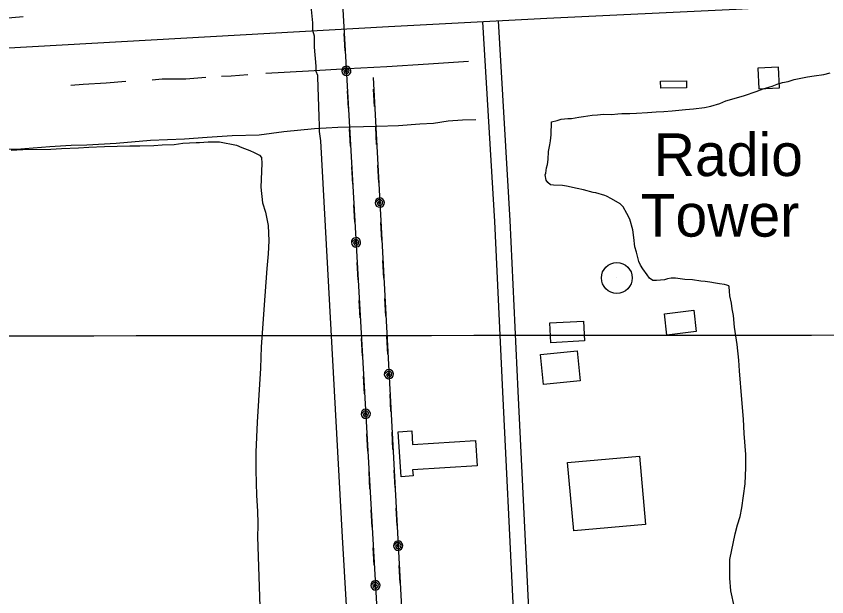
# Model space of a CAD drawing. Extents: x 3297716 to 3335574, y 688621 to 713991.
# Drawn here: x 3314736 to 3316312, y 708656 to 709785 of the extents above; entities that cross this region are included whole.
import ezdxf

# ---------------------------------------------------------------- set-up
doc = ezdxf.new("R2010")
doc.units = 0
for name, color, linetype in [('V-BLDG-OTLN', 7, 'Continuous'), ('V-GRID-MAJR', 7, 'Continuous'), ('V-ROAD-CNTR', 7, 'Continuous'), ('V-SITE-VEGE', 7, 'Continuous'), ('V-TOPO-SHOR', 7, 'Continuous'), ('V-TOPO-TOWR', 7, 'Continuous'), ('V-TOPO-TOWR-IDEN', 7, 'Continuous'), ('V-UTIL-LINE', 7, 'Continuous')]:
    doc.layers.add(name, color=color, linetype=linetype)

msp = doc.modelspace()

# ---------------------------------------------------------------- linework, layer by layer
at = {"layer": 'V-BLDG-OTLN'}
for points in [[(3316218.3325259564, 709685.3546023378), (3316178.382605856, 709683.3426063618), (3316180.39560183, 709643.39368626), (3316220.3445219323, 709645.405682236)], [(3315989.273984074, 709658.4176562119), (3316039.2688840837, 709659.0846548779), (3316039.45588371, 709645.085682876), (3315989.459983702, 709644.4196842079)], [(3315996.468969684, 709205.845561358), (3316053.463855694, 709212.7065476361), (3316058.452845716, 709171.2626305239), (3316001.4579597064, 709164.4016442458)], [(3315841.0712804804, 709153.1896666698), (3315775.5654114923, 709149.7616735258), (3315773.549415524, 709188.285596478), (3315839.055284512, 709191.713589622)], [(3315833.012296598, 709075.461822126), (3315761.378439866, 709068.3098364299), (3315755.5644514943, 709126.5387199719), (3315827.198308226, 709133.6917056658)], [(3315507.0640000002, 708951.895), (3315629.5470000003, 708959.637), (3315632.666, 708910.272), (3315507.111, 708902.338), (3315507.858, 708890.5), (3315484.728, 708889.04), (3315479.207, 708976.406), (3315505.411, 708978.058)], [(3315959.65604331, 708796.4103802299), (3315820.252322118, 708784.007405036), (3315808.4523457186, 708916.6331397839), (3315947.85606691, 708929.0361149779)]]:
    msp.add_lwpolyline(points, close=True, dxfattribs=at)
at = {"layer": 'V-GRID-MAJR'}
msp.add_spline([(3301840.245, 709153.404), (3307091.973, 709156.841), (3312343.699, 709161.042), (3317595.4250000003, 709166.008), (3322847.151, 709171.736), (3328098.875, 709178.229), (3333350.598, 709185.486), (3333350.599, 709185.486)], degree=3, dxfattribs=at)
at = {"layer": 'V-ROAD-CNTR'}
for points in [[(3321969.11902436, 710116.1787406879), (3321666.245630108, 710108.8057554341), (3321492.746977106, 710098.0457769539), (3321073.9358147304, 710068.725835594), (3320654.183654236, 710049.840873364), (3320230.1515023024, 710028.8209154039), (3319711.4135397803, 709997.8059774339), (3319431.537099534, 709981.7200096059), (3319189.123584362, 709967.2580385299), (3318433.2280961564, 709928.030116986), (3318142.237678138, 709911.7191496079), (3317361.76323909, 709865.509242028), (3316719.677523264, 709830.5803118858), (3316136.331689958, 709797.4653781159), (3315767.733427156, 709780.235412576), (3315460.47704167, 709764.0894448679), (3314594.6517733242, 709715.615541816), (3313764.1424343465, 709666.735639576), (3313139.8856828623, 709630.3297123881), (3312580.6778012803, 709600.1097728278), (3311894.166174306, 709563.750845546), (3311218.8075250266, 709524.6229238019), (3310603.397755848, 709491.00399104), (3310297.884366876, 709478.5810158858)], [(3315643.158676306, 709773.591425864), (3315666.083630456, 709385.522202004), (3315681.919598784, 709054.0518649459), (3315701.758559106, 708643.1946866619), (3315726.4265097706, 708269.513434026), (3315739.108484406, 708212.2485485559), (3315764.9624326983, 708155.707661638), (3315803.2323561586, 708088.212796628), (3315841.983278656, 708033.1759067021), (3315900.6751612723, 707990.2989924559), (3316040.284882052, 707884.6312037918), (3316095.7847710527, 707831.3283103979), (3316137.516687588, 707782.1574087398), (3316169.0516245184, 707726.604519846), (3316190.167582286, 707676.48762008), (3316201.601559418, 707620.7597315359), (3316210.474541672, 707465.8600413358), (3316221.8445189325, 707144.790683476), (3316229.917502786, 706954.1030648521)], [(3315673.1066164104, 709775.361422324), (3315696.04157054, 709387.1221988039), (3315711.885538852, 709055.4918620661), (3315731.710499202, 708644.906683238), (3315756.210450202, 708273.769425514), (3315767.7124271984, 708221.8365293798), (3315791.7023792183, 708169.3696343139), (3315828.6063054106, 708104.2847644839), (3315863.669235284, 708054.4858640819), (3315918.5771254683, 708014.3729443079), (3316059.794843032, 707907.4891580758), (3316117.668727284, 707851.9062692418), (3316162.214638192, 707799.4193742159), (3316196.011570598, 707739.8784932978), (3316218.9615246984, 707685.411602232), (3316231.4274997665, 707624.6537237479), (3316240.4444817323, 707467.2480385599), (3316251.822458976, 707145.956681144), (3316259.8914428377, 706955.371062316)]]:
    msp.add_lwpolyline(points, dxfattribs=at)
at = {"layer": 'V-SITE-VEGE'}
for points in [[(3315923.807, 709401.017), (3315916.5, 709413.66), (3315910.237, 709419.759), (3315893.714, 709429.509), (3315884.154, 709434.435), (3315880.9590000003, 709435.86), (3315862.9590000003, 709441.1190000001), (3315857.79, 709441.971), (3315839.143, 709447.255), (3315826.884, 709449.688), (3315806.2600000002, 709454.397), (3315798.4960000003, 709455.351), (3315780.967, 709456.037), (3315775.149, 709456.9180000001), (3315770.109, 709461.0160000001), (3315766.392, 709465.714), (3315764.852, 709476.177), (3315766.2770000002, 709479.372), (3315767.3340000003, 709489.737), (3315769.538, 709496.149), (3315770.568, 709505.863), (3315771.178, 709521.444), (3315773.636, 709534.353), (3315775.239, 709542.0920000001), (3315776.347, 709553.751), (3315777.34, 709579.071), (3315787.857, 709581.909), (3315795.7460000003, 709584.201), (3315808.808, 709585.6410000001), (3315815.9760000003, 709586.007), (3315830.359, 709588.045), (3315839.526, 709589.636), (3315855.883, 709592.245), (3315866.322, 709593.136), (3315878.057, 709593.976), (3315893.6380000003, 709593.366), (3315906.051, 709594.83), (3315913.8680000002, 709595.172), (3315929.472, 709595.213), (3315942.5100000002, 709595.9990000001), (3315964.0100000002, 709597.107), (3315980.316, 709598.4180000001), (3315995.299, 709599.131), (3316011.605, 709600.441), (3316037.727, 709603.319), (3316053.384, 709604.654), (3316074.286, 709607.085), (3316086.748, 709609.848), (3316104.506, 709615.003), (3316115.748, 709619.764), (3316136.801, 709626.091), (3316152.5870000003, 709630.672), (3316174.99, 709638.248), (3316188.853, 709643.556), (3316205.9620000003, 709648.735), (3316215.8540000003, 709652.25), (3316226.393, 709655.737), (3316236.8850000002, 709657.927), (3316248.72, 709661.363), (3316258.561, 709663.577), (3316274.9450000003, 709666.838), (3316287.383, 709668.949), (3316306.3370000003, 709671.458), (3316318.799, 709674.221)], [(3314726.3910000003, 709524.0650000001), (3314749.1890000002, 709525.12), (3314803.85, 709526.228), (3314824.699, 709527.361), (3314857.2660000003, 709528.684), (3314877.466, 709529.843), (3314908.0810000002, 709531.242), (3314957.549, 709532.552), (3314977.0500000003, 709532.438), (3315003.741, 709533.343), (3315020.052, 709534.654), (3315043.474, 709535.035), (3315060.481, 709537.617), (3315086.5500000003, 709539.196), (3315093.042, 709538.942), (3315109.35, 709540.253), (3315117.815, 709540.5700000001), (3315131.448, 709540.036), (3315164.356, 709533.544), (3315175.239, 709529.214), (3315190.615, 709523.41), (3315198.93, 709519.832), (3315209.113, 709514.233), (3315213.504, 709510.16), (3315213.694, 709498.447), (3315211.8880000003, 709452.353), (3315215.234, 709421.661), (3315221.014, 709403.229), (3315226.512, 709377.656), (3315227.289, 709347.714), (3315226.295, 709322.397), (3315223.877, 709293.88), (3315219.84, 709240.723), (3315212.699, 709141.52), (3315211.068, 709099.97), (3315207.3000000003, 709037.047), (3315204.994, 708994.875), (3315202.082, 708937.1190000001), (3315202.002, 708902.01), (3315203.313, 708852.5430000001), (3315205.363, 708821.902), (3315206.3680000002, 708797.806), (3315205.221, 708768.591), (3315206.088, 708757.503), (3315205.934, 708753.608), (3315209.7660000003, 708635.77)], [(3316133.023, 708634.664), (3316125.857, 708667.457), (3316123.553, 708691.605), (3316123.682, 708728.012), (3316134.106, 708778.319), (3316138.69, 708795.694), (3316143.8710000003, 708811.746), (3316147.129, 708828.5260000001), (3316153.509, 708875.089), (3316154.756, 708906.9010000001), (3316155.1, 708932.247), (3316151.5100000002, 708973.35), (3316150.634, 709000.6950000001), (3316146.941, 709039.201), (3316142.6380000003, 709095.2880000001), (3316141.481, 709115.4890000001), (3316138.1350000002, 709146.181), (3316132.965, 709180.196), (3316130.586, 709202.3960000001), (3316128.4990000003, 709215.483), (3316126.983, 709226.595), (3316123.647, 709241.03), (3316123.358, 709250.145), (3316122.3880000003, 709258.636), (3316121.8140000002, 709260.609), (3316117.9450000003, 709261.411), (3316113.452, 709262.886), (3316103.738, 709263.9180000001), (3316095.9990000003, 709265.524), (3316085.014, 709267.254), (3316075.9760000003, 709268.909), (3316067.536, 709269.241), (3316051.381, 709271.824), (3316036.449, 709272.409), (3316018.349, 709275.072), (3316009.909, 709275.4010000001), (3316002.69, 709273.734), (3315996.771, 709272.014), (3315981.114, 709270.679), (3315973.973, 709270.959), (3315967.632, 709275.111), (3315963.344, 709281.781), (3315954.687, 709293.174), (3315949.774, 709300.518), (3315946.808, 709307.786), (3315945.166, 709315.655), (3315942.303, 709325.52), (3315938.813, 709336.059), (3315936.931, 709354.339), (3315934.9220000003, 709369.3740000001), (3315929.216, 709389.753), (3315923.807, 709401.017)]]:
    msp.add_lwpolyline(points, dxfattribs=at)
at = {"layer": 'V-TOPO-SHOR'}
for points in [[(3314749.799, 709783.17), (3314697.727, 709778.763), (3314643.127, 709775.175), (3314600.193, 709770.829), (3314542.401, 709768.39)], [(3315615.6180000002, 709696.265), (3315537.884, 709691.27), (3315456.97, 709686.355), (3315380.944, 709682.296), (3315304.906, 709677.751), (3315221.411, 709673.338)], [(3315104.968, 709665.144), (3315066.031, 709661.937), (3315020.279, 709662.037), (3315000.835, 709660.157)], [(3315186.822, 709670.653), (3315170.364, 709669.226), (3315154.275, 709668.142), (3315135.614, 709667.485)], [(3314949.647, 709657.861), (3314911.069, 709654.376), (3314866.72, 709652.01), (3314842.826, 709650.136)], [(3315629.774, 709583.007), (3315603.957, 709582.1510000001), (3315576.17, 709580.3690000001), (3315547.3540000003, 709576.177), (3315521.039, 709574.848), (3315479.586, 709571.4400000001), (3315437.205, 709570), (3315411.4, 709569.631), (3315361.711, 709567.876), (3315316.389, 709565.533), (3315256.38, 709559.639), (3315208.537, 709553.46), (3315156.414, 709551.763), (3315107.677, 709549.01), (3315063.303, 709545.67), (3314997.528, 709542.833), (3314930.71, 709537.099), (3314873.6890000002, 709534.056), (3314843.008, 709533.314), (3314801.577, 709530.879), (3314737.1920000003, 709525.087), (3314688.544, 709526.228)]]:
    msp.add_lwpolyline(points, dxfattribs=at)
at = {"layer": 'V-TOPO-TOWR'}
msp.add_line((3315904.0312635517, 709275.5889501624), (3315904.0312635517, 709275.5889501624), dxfattribs=at)
msp.add_circle((3315904.0312635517, 709275.5889501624), 30.000000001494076, dxfattribs=at)
at = {"layer": 'V-UTIL-LINE'}
for points in [[(3315264.019, 711804.143), (3315332.81, 710592.664), (3315359.733, 710004.734), (3315464.0130000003, 708160.701), (3315531.114, 706954.474), (3315629.2970000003, 706041.242), (3315627.089, 705388.669), (3315661.707, 704739.828), (3315220.474, 703613.16)], [(3315386.648, 708494.902), (3315370.6240000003, 708771.294), (3315328.933, 709542.286), (3315325.73, 709560.448), (3315325.728, 709564.1), (3315325.72, 709571.38), (3315325.703, 709589.544), (3315322.486, 709665.947), (3315322.482, 709669.551), (3315319.352, 709676.8520000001), (3315319.348, 709680.457), (3315319.346, 709684.086), (3315319.342, 709687.76), (3315316.123, 709724.112), (3315316.112, 709735.02), (3315316.102, 709745.927), (3315312.948, 709756.833), (3315312.934, 709771.394), (3315309.7800000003, 709804.115)], [(3315375.986, 709717.301), (3315374.0670000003, 709751.247)], [(3315378.19, 709678.345), (3315375.921, 709676.577), (3315378.145, 709675.893), (3315380.268, 709677.635), (3315379.7800000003, 709680.522), (3315376.382, 709680.491), (3315373.1750000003, 709677.071), (3315375.169, 709673.299), (3315379.923, 709672.272), (3315383.139, 709675.53), (3315383.861, 709679.942), (3315380.5840000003, 709683.482), (3315375.079, 709683.4940000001), (3315369.205, 709677.836), (3315370.083, 709674.437), (3315372.196, 709671.631), (3315375.221, 709669.848), (3315378.698, 709669.359), (3315382.098, 709670.237), (3315384.903, 709672.35), (3315386.686, 709675.376), (3315387.176, 709678.853), (3315386.298, 709682.253), (3315384.185, 709685.058), (3315381.159, 709686.841), (3315377.682, 709687.33), (3315374.282, 709686.452), (3315371.477, 709684.339), (3315369.694, 709681.314), (3315369.205, 709677.836)], [(3315430.1380000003, 709665.111), (3315533.453, 707737.333), (3315596.287, 706607.287)], [(3315382.31, 709605.479), (3315380.39, 709639.425)], [(3315433.153, 709608.849), (3315431.3340000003, 709642.8)], [(3315386.487, 709531.5970000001), (3315384.568, 709565.5430000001)], [(3315437.113, 709534.956), (3315435.294, 709568.907)], [(3315390.665, 709457.716), (3315388.745, 709491.662)], [(3315441.073, 709461.062), (3315439.254, 709495.013)], [(3315443.161, 709422.116), (3315440.886, 709420.354), (3315443.108, 709419.664), (3315445.236, 709421.4), (3315444.757, 709424.2880000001), (3315441.359, 709424.267), (3315438.142, 709420.857), (3315440.125, 709417.079), (3315444.876, 709416.0380000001), (3315448.1010000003, 709419.287), (3315448.836, 709423.697), (3315445.5700000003, 709427.246), (3315440.0640000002, 709427.274), (3315434.174, 709421.634), (3315435.042, 709418.232), (3315437.146, 709415.42), (3315440.167, 709413.628), (3315443.642, 709413.129), (3315447.045, 709413.997), (3315449.856, 709416.101), (3315451.648, 709419.122), (3315452.148, 709422.5970000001), (3315451.2800000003, 709426), (3315449.1750000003, 709428.811), (3315446.1550000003, 709430.603), (3315442.679, 709431.103), (3315439.2770000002, 709430.234), (3315436.465, 709428.13), (3315434.673, 709425.11), (3315434.174, 709421.634)], [(3315394.843, 709383.834), (3315392.923, 709417.78)], [(3315447.0670000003, 709349.223), (3315445.247, 709383.174)], [(3315397.048, 709344.878), (3315394.778, 709343.11), (3315397.002, 709342.427), (3315399.125, 709344.1680000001), (3315398.637, 709347.056), (3315395.24, 709347.025), (3315392.0330000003, 709343.605), (3315394.0270000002, 709339.833), (3315398.7800000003, 709338.805), (3315401.997, 709342.064), (3315402.719, 709346.476), (3315399.4420000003, 709350.0160000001), (3315393.936, 709350.028), (3315388.062, 709344.37), (3315388.941, 709340.97), (3315391.053, 709338.165), (3315394.079, 709336.382), (3315397.556, 709335.893), (3315400.9560000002, 709336.7710000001), (3315403.761, 709338.884), (3315405.544, 709341.909), (3315406.0330000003, 709345.386), (3315405.1550000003, 709348.786), (3315403.042, 709351.591), (3315400.017, 709353.375), (3315396.54, 709353.8640000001), (3315393.14, 709352.986), (3315390.335, 709350.873), (3315388.552, 709347.8470000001), (3315388.062, 709344.37)], [(3315401.167, 709272.012), (3315399.247, 709305.958)], [(3315451.0270000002, 709275.329), (3315449.208, 709309.28)], [(3315454.987, 709201.436), (3315453.168, 709235.387)], [(3315405.345, 709198.13), (3315403.4250000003, 709232.076)], [(3315409.523, 709124.2490000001), (3315407.603, 709158.1950000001)], [(3315458.947, 709127.542), (3315457.128, 709161.493)], [(3315461.035, 709088.595), (3315458.7600000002, 709086.834), (3315460.982, 709086.144), (3315463.11, 709087.879), (3315462.631, 709090.768), (3315459.233, 709090.747), (3315456.0160000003, 709087.337), (3315457.9990000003, 709083.559), (3315462.75, 709082.517), (3315465.9760000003, 709085.767), (3315466.711, 709090.176), (3315463.444, 709093.726), (3315457.9390000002, 709093.754), (3315452.048, 709088.1140000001), (3315452.916, 709084.711), (3315455.021, 709081.9), (3315458.041, 709080.108), (3315461.517, 709079.608), (3315464.919, 709080.4770000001), (3315467.731, 709082.581), (3315469.522, 709085.601), (3315470.022, 709089.077), (3315469.154, 709092.479), (3315467.049, 709095.291), (3315464.029, 709097.083), (3315460.553, 709097.582), (3315457.151, 709096.714), (3315454.34, 709094.61), (3315452.548, 709091.589), (3315452.048, 709088.1140000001)], [(3315413.701, 709050.367), (3315411.781, 709084.313)], [(3315464.94, 709015.703), (3315463.1210000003, 709049.654)], [(3315415.9050000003, 709011.412), (3315413.636, 709009.644), (3315415.86, 709008.961), (3315417.983, 709010.702), (3315417.495, 709013.589), (3315414.097, 709013.558), (3315410.89, 709010.139), (3315412.884, 709006.366), (3315417.6380000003, 709005.339), (3315420.8540000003, 709008.598), (3315421.576, 709013.01), (3315418.299, 709016.549), (3315412.794, 709016.562), (3315406.92, 709010.904), (3315407.798, 709007.504), (3315409.911, 709004.699), (3315412.936, 709002.916), (3315416.413, 709002.426), (3315419.813, 709003.305), (3315422.6180000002, 709005.4180000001), (3315424.4020000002, 709008.443), (3315424.8910000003, 709011.92), (3315424.0130000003, 709015.3200000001), (3315421.9, 709018.125), (3315418.8740000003, 709019.908), (3315415.397, 709020.398), (3315411.997, 709019.519), (3315409.1920000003, 709017.407), (3315407.409, 709014.381), (3315406.92, 709010.904)], [(3315420.025, 708938.545), (3315418.105, 708972.491)], [(3315468.9, 708941.809), (3315467.0810000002, 708975.76)], [(3315424.203, 708864.6630000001), (3315422.2830000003, 708898.609)], [(3315472.86, 708867.916), (3315471.041, 708901.867)], [(3315428.381, 708790.782), (3315426.461, 708824.728)], [(3315476.821, 708794.022), (3315475.001, 708827.973)], [(3315478.909, 708755.0750000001), (3315476.634, 708753.314), (3315478.856, 708752.6240000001), (3315480.985, 708754.359), (3315480.505, 708757.247), (3315477.108, 708757.2270000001), (3315473.8910000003, 708753.817), (3315475.8740000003, 708750.0380000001), (3315480.6240000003, 708748.997), (3315483.85, 708752.246), (3315484.585, 708756.656), (3315481.318, 708760.205), (3315475.813, 708760.234), (3315469.9220000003, 708754.593), (3315470.791, 708751.191), (3315472.895, 708748.379), (3315475.915, 708746.588), (3315479.3910000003, 708746.088), (3315482.793, 708746.956), (3315485.605, 708749.061), (3315487.397, 708752.081), (3315487.896, 708755.557), (3315487.028, 708758.959), (3315484.924, 708761.77), (3315481.903, 708763.562), (3315478.428, 708764.062), (3315475.025, 708763.194), (3315472.214, 708761.089), (3315470.4220000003, 708758.069), (3315469.9220000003, 708754.593)], [(3315432.559, 708716.9), (3315430.639, 708750.846)], [(3315482.8140000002, 708682.183), (3315480.995, 708716.134)], [(3315434.7630000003, 708677.946), (3315432.4930000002, 708676.1780000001), (3315434.717, 708675.4940000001), (3315436.84, 708677.236), (3315436.352, 708680.123), (3315432.955, 708680.0920000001), (3315429.748, 708676.6730000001), (3315431.742, 708672.9), (3315436.495, 708671.873), (3315439.7120000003, 708675.132), (3315440.434, 708679.544), (3315437.157, 708683.083), (3315431.651, 708683.095), (3315425.7770000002, 708677.438), (3315426.656, 708674.0380000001), (3315428.768, 708671.233), (3315431.794, 708669.4500000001), (3315435.271, 708668.96), (3315438.671, 708669.839), (3315441.4760000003, 708671.951), (3315443.259, 708674.9770000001), (3315443.748, 708678.454), (3315442.87, 708681.854), (3315440.757, 708684.659), (3315437.732, 708686.442), (3315434.255, 708686.932), (3315430.855, 708686.0530000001), (3315428.0500000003, 708683.9400000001), (3315426.267, 708680.915), (3315425.7770000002, 708677.438)]]:
    msp.add_lwpolyline(points, dxfattribs=at)

# ---------------------------------------------------------------- texts
at = {"layer": 'V-TOPO-TOWR-IDEN'}
for s, height, p in [('Radio', 82.99983200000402, (3315975.797725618, 709473.7771111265)), ('Tower', 82.999998, (3315950.2708135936, 709355.9106835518))]:
    msp.add_text(s, height=height, dxfattribs=at).set_placement(p)

doc.saveas('drawing.dxf')
